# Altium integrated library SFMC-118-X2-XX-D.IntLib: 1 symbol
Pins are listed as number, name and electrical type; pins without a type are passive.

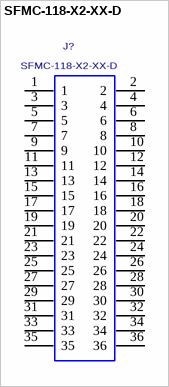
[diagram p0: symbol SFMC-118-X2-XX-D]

## SFMC-118-X2-XX-D
designator J?
0.050" CUTTABLE SOCKET STRIP, DOUBLE ROW ASSEMBLY.; MANUFACTURER: SAMTEC
footprint SFMC-118-X2-XX-D
pins: 1, 2, 3, 4, 5, 6, 7, 8, 9, 10, 11, 12, 13, 14, 15, 16, 17, 18, 19, 20, 21, 22, 23, 24, 25, 26, 27, 28, 29, 30, 31, 32, 33, 34, 35, 36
